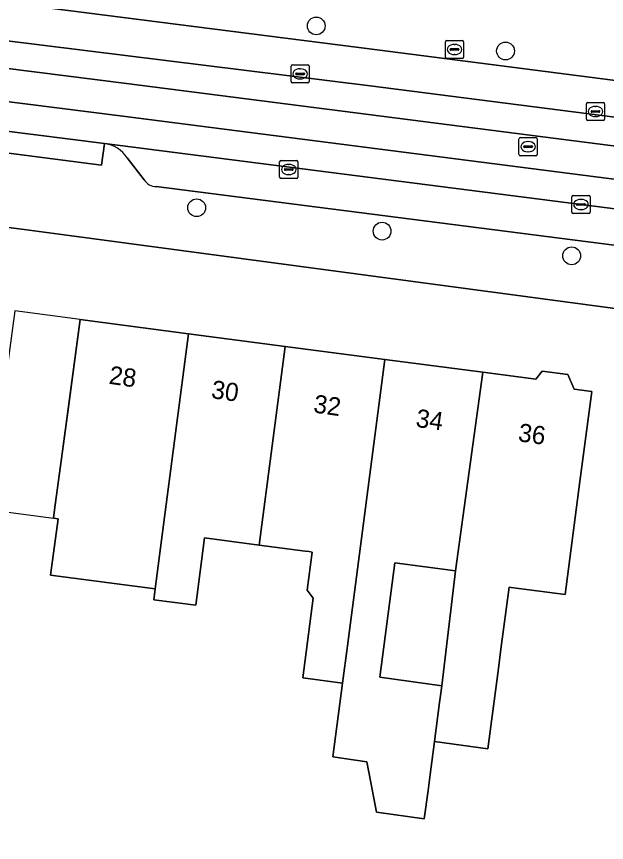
# Model space of a CAD drawing. Extents: x 161692 to 162379, y 380760 to 381678.
# Drawn here: x 161918.27 to 161950.72, y 381271.3 to 381316.74 of the extents above; entities that cross this region are included whole.
import ezdxf

# ---------------------------------------------------------------- set-up
doc = ezdxf.new("R2010")
doc.units = 0
for name, color, linetype in [('IMGEO_Boom', 7, 'Continuous'), ('IMGEO_Brandkraan', 7, 'Continuous'), ('IMGEO_Erf', 7, 'Continuous'), ('IMGEO_Kolk', 7, 'Continuous'), ('IMGEO_Pand', 7, 'Continuous'), ('IMGEO_Pand_nummerreeks', 7, 'Continuous'), ('IMGEO_Pand_overbouw', 7, 'Continuous'), ('IMGEO_Parkeervlak_open', 7, 'Continuous'), ('IMGEO_Rijbaan_lokaal_gesloten', 7, 'Continuous'), ('IMGEO_Rijbaan_lokaal_open', 7, 'Continuous'), ('IMGEO_Rioolput', 7, 'Continuous'), ('IMGEO_Voetpad_open', 7, 'Continuous')]:
    doc.layers.add(name, color=color, linetype=linetype)

msp = doc.modelspace()

# ---------------------------------------------------------------- linework, layer by layer
at = {"layer": 'IMGEO_Boom'}
for centre in [(161934.757, 381316.222), (161945.167, 381314.846), (161928.182, 381306.22), (161938.377, 381304.933), (161948.805, 381303.574)]:
    msp.add_circle(centre, 0.489, dxfattribs=at)
at = {"layer": 'IMGEO_Brandkraan'}
for p, q in [((161941.934, 381315.43), (161942.786, 381315.43)), ((161941.859, 381314.504), (161941.859, 381315.356)), ((161942.118, 381314.924), (161942.118, 381314.936)), ((161942.161, 381314.973), (161942.559, 381314.973)), ((161942.347, 381315.21), (161942.372, 381315.21)), ((161942.602, 381314.936), (161942.602, 381314.924)), ((161942.86, 381315.356), (161942.86, 381314.504)), ((161942.556, 381314.887), (161942.158, 381314.887)), ((161942.37, 381314.65), (161942.345, 381314.65)), ((161942.786, 381314.43), (161941.934, 381314.43))]:
    msp.add_line(p, q, dxfattribs=at)
for points in [[(161941.934, 381315.43), (161942.786, 381315.43)], [(161941.859, 381314.504), (161941.859, 381315.356)], [(161942.86, 381315.356), (161942.86, 381314.504)], [(161942.786, 381314.43), (161941.934, 381314.43)]]:
    msp.add_lwpolyline(points, dxfattribs=at)
for centre, radius, start, end in [((161941.936, 381315.354), 0.0765, 91.552, 178.448), ((161941.936, 381315.354), 0.0765, 91.552, 178.448), ((161942.784, 381315.354), 0.0765, 1.552, 88.448), ((161942.784, 381315.354), 0.0765, 1.552, 88.448), ((161942.158, 381314.933), 0.0403, 85.8775, 175.7526), ((161942.563, 381314.935), 0.0386, 1.7309, 96.639), ((161941.936, 381314.506), 0.0765, 181.552, 268.448), ((161941.936, 381314.506), 0.0765, 181.552, 268.448), ((161942.155, 381314.923), 0.0366, 178.938, 274.7102), ((161942.559, 381314.93), 0.043, 264.8664, 352.4533), ((161942.784, 381314.506), 0.0765, 271.552, 358.448), ((161942.784, 381314.506), 0.0765, 271.552, 358.448)]:
    msp.add_arc(centre, radius, start, end, dxfattribs=at)
for centre, major_axis, ratio, start_param, end_param in [((161942.346, 381314.93), (-0.387, 0.002), 0.722429, 4.712389, 7.853982), ((161942.371, 381314.93), (-0.39, 0.002), 0.717154, 1.570796, 4.712389)]:
    msp.add_ellipse(centre, major_axis=major_axis, ratio=ratio, start_param=start_param, end_param=end_param, dxfattribs=at)
at = {"layer": 'IMGEO_Erf'}
msp.add_lwpolyline([(161867.852, 381207.538), (161977.201, 381250), (161995.053, 381256.932), (162000, 381258.853), (162011.546, 381263.36), (162015.076, 381292.22), (162000, 381294.145), (161921.176, 381304.696), (161918.702, 381305.015), (161871.402, 381311.107)], dxfattribs=at)
for points in [[(161936.202, 381280.054), (161934.023, 381280.36), (161934.594, 381284.745), (161934.254, 381285.183), (161934.527, 381287.278), (161934.374, 381287.298), (161934.15, 381287.327), (161931.624, 381287.657), (161928.615, 381288.051), (161928.132, 381284.353), (161925.822, 381284.655), (161925.899, 381285.247), (161920.139, 381286.001), (161920.559, 381289.105), (161920.299, 381289.139), (161920.36, 381289.591), (161921.106, 381295.112), (161921.775, 381300.067), (161927.732, 381299.288), (161933.052, 381298.591), (161938.529, 381297.875), (161943.91, 381297.171), (161946.835, 381296.788), (161947.176, 381297.233), (161948.599, 381297.047), (161948.933, 381296.242), (161949.909, 381296.114), (161949.26, 381291.157), (161948.447, 381284.941), (161945.482, 381285.322), (161945.36, 381285.338), (161944.916, 381281.938), (161944.777, 381280.872), (161944.199, 381276.447), (161941.258, 381276.859), (161941.021, 381275.043), (161940.904, 381274.147), (161940.701, 381272.592), (161938.076, 381272.96), (161937.756, 381274.589), (161937.53, 381275.74), (161935.674, 381276)], [(161942.415, 381286.245), (161939.084, 381286.681), (161938.263, 381280.386), (161941.656, 381279.91)]]:
    msp.add_lwpolyline(points, close=True, dxfattribs=at)
at = {"layer": 'IMGEO_Kolk'}
for p, q in [((161933.444, 381314.084), (161934.296, 381314.084)), ((161933.369, 381313.158), (161933.369, 381314.01)), ((161933.628, 381313.578), (161933.628, 381313.59)), ((161933.671, 381313.627), (161934.069, 381313.627)), ((161933.857, 381313.864), (161933.882, 381313.864)), ((161934.112, 381313.59), (161934.112, 381313.578)), ((161934.37, 381314.01), (161934.37, 381313.158)), ((161934.066, 381313.541), (161933.668, 381313.541)), ((161933.88, 381313.304), (161933.855, 381313.304)), ((161934.296, 381313.084), (161933.444, 381313.084)), ((161949.613, 381311.089), (161949.613, 381311.941)), ((161949.688, 381312.015), (161950.54, 381312.015)), ((161950.101, 381311.795), (161950.126, 381311.795)), ((161950.614, 381311.941), (161950.614, 381311.089)), ((161949.872, 381311.509), (161949.872, 381311.521)), ((161950.31, 381311.472), (161949.912, 381311.472)), ((161949.915, 381311.558), (161950.313, 381311.558)), ((161950.356, 381311.521), (161950.356, 381311.509)), ((161950.54, 381311.015), (161949.688, 381311.015)), ((161950.124, 381311.235), (161950.099, 381311.235)), ((161932.744, 381307.898), (161932.744, 381308.75)), ((161932.819, 381308.824), (161933.671, 381308.824)), ((161933.232, 381308.604), (161933.257, 381308.604)), ((161933.745, 381308.75), (161933.745, 381307.898)), ((161933.003, 381308.318), (161933.003, 381308.33)), ((161933.441, 381308.281), (161933.043, 381308.281)), ((161933.046, 381308.367), (161933.444, 381308.367)), ((161933.487, 381308.33), (161933.487, 381308.318)), ((161933.671, 381307.824), (161932.819, 381307.824)), ((161933.255, 381308.044), (161933.23, 381308.044)), ((161948.816, 381305.973), (161948.816, 381306.825)), ((161948.891, 381306.899), (161949.743, 381306.899)), ((161949.817, 381306.825), (161949.817, 381305.973)), ((161949.075, 381306.393), (161949.075, 381306.405)), ((161949.513, 381306.356), (161949.115, 381306.356)), ((161949.118, 381306.442), (161949.516, 381306.442)), ((161949.304, 381306.679), (161949.329, 381306.679)), ((161949.559, 381306.405), (161949.559, 381306.393)), ((161949.743, 381305.899), (161948.891, 381305.899)), ((161949.327, 381306.119), (161949.302, 381306.119))]:
    msp.add_line(p, q, dxfattribs=at)
for points in [[(161933.444, 381314.084), (161934.296, 381314.084)], [(161933.369, 381313.158), (161933.369, 381314.01)], [(161934.37, 381314.01), (161934.37, 381313.158)], [(161934.296, 381313.084), (161933.444, 381313.084)], [(161949.613, 381311.089), (161949.613, 381311.941)], [(161949.688, 381312.015), (161950.54, 381312.015)], [(161950.614, 381311.941), (161950.614, 381311.089)], [(161950.54, 381311.015), (161949.688, 381311.015)], [(161932.744, 381307.898), (161932.744, 381308.75)], [(161932.819, 381308.824), (161933.671, 381308.824)], [(161933.745, 381308.75), (161933.745, 381307.898)], [(161933.671, 381307.824), (161932.819, 381307.824)], [(161948.816, 381305.973), (161948.816, 381306.825)], [(161948.891, 381306.899), (161949.743, 381306.899)], [(161949.817, 381306.825), (161949.817, 381305.973)], [(161949.743, 381305.899), (161948.891, 381305.899)]]:
    msp.add_lwpolyline(points, dxfattribs=at)
for centre, radius, start, end in [((161933.446, 381314.008), 0.0765, 91.552, 178.448), ((161933.446, 381314.008), 0.0765, 91.552, 178.448), ((161934.294, 381314.008), 0.0765, 1.552, 88.448), ((161934.294, 381314.008), 0.0765, 1.552, 88.448), ((161933.668, 381313.587), 0.0403, 85.8775, 175.7526), ((161933.665, 381313.577), 0.0366, 178.938, 274.7102), ((161934.069, 381313.584), 0.043, 264.8664, 352.4533), ((161934.073, 381313.589), 0.0386, 1.7309, 96.639), ((161933.446, 381313.16), 0.0765, 181.552, 268.448), ((161933.446, 381313.16), 0.0765, 181.552, 268.448), ((161934.294, 381313.16), 0.0765, 271.552, 358.448), ((161934.294, 381313.16), 0.0765, 271.552, 358.448), ((161949.69, 381311.939), 0.0765, 91.552, 178.448), ((161949.69, 381311.939), 0.0765, 91.552, 178.448), ((161950.538, 381311.939), 0.0765, 1.552, 88.448), ((161950.538, 381311.939), 0.0765, 1.552, 88.448), ((161949.912, 381311.518), 0.0403, 85.8775, 175.7526), ((161949.909, 381311.508), 0.0366, 178.938, 274.7102), ((161950.313, 381311.515), 0.043, 264.8664, 352.4533), ((161950.317, 381311.52), 0.0386, 1.7309, 96.639), ((161949.69, 381311.091), 0.0765, 181.552, 268.448), ((161949.69, 381311.091), 0.0765, 181.552, 268.448), ((161950.538, 381311.091), 0.0765, 271.552, 358.448), ((161950.538, 381311.091), 0.0765, 271.552, 358.448), ((161932.821, 381308.748), 0.0765, 91.552, 178.448), ((161932.821, 381308.748), 0.0765, 91.552, 178.448), ((161933.669, 381308.748), 0.0765, 1.552, 88.448), ((161933.669, 381308.748), 0.0765, 1.552, 88.448), ((161933.043, 381308.327), 0.0403, 85.8775, 175.7526), ((161933.04, 381308.317), 0.0366, 178.938, 274.7102), ((161933.444, 381308.324), 0.043, 264.8664, 352.4533), ((161933.448, 381308.329), 0.0386, 1.7309, 96.639), ((161932.821, 381307.9), 0.0765, 181.552, 268.448), ((161932.821, 381307.9), 0.0765, 181.552, 268.448), ((161933.669, 381307.9), 0.0765, 271.552, 358.448), ((161933.669, 381307.9), 0.0765, 271.552, 358.448), ((161948.893, 381306.823), 0.0765, 91.552, 178.448), ((161948.893, 381306.823), 0.0765, 91.552, 178.448), ((161949.741, 381306.823), 0.0765, 1.552, 88.448), ((161949.741, 381306.823), 0.0765, 1.552, 88.448), ((161949.115, 381306.402), 0.0403, 85.8775, 175.7526), ((161949.112, 381306.392), 0.0366, 178.938, 274.7102), ((161949.516, 381306.399), 0.043, 264.8664, 352.4533), ((161949.52, 381306.404), 0.0386, 1.7309, 96.639), ((161948.893, 381305.975), 0.0765, 181.552, 268.448), ((161948.893, 381305.975), 0.0765, 181.552, 268.448), ((161949.741, 381305.975), 0.0765, 271.552, 358.448), ((161949.741, 381305.975), 0.0765, 271.552, 358.448)]:
    msp.add_arc(centre, radius, start, end, dxfattribs=at)
for centre, major_axis, ratio, start_param, end_param in [((161933.856, 381313.584), (-0.387, 0.002), 0.722429, 4.712389, 7.853982), ((161933.881, 381313.584), (-0.39, 0.002), 0.717154, 1.570796, 4.712389), ((161950.1, 381311.515), (-0.387, 0.002), 0.722429, 4.712389, 7.853982), ((161950.125, 381311.515), (-0.39, 0.002), 0.717154, 1.570796, 4.712389), ((161933.231, 381308.324), (-0.387, 0.002), 0.722429, 4.712389, 7.853982), ((161933.256, 381308.324), (-0.39, 0.002), 0.717154, 1.570796, 4.712389), ((161949.303, 381306.399), (-0.387, 0.002), 0.722429, 4.712389, 7.853982), ((161949.328, 381306.399), (-0.39, 0.002), 0.717154, 1.570796, 4.712389)]:
    msp.add_ellipse(centre, major_axis=major_axis, ratio=ratio, start_param=start_param, end_param=end_param, dxfattribs=at)
at = {"layer": 'IMGEO_Pand'}
for points in [[(161927.732, 381299.288), (161921.775, 381300.067), (161921.106, 381295.112), (161920.36, 381289.591), (161920.299, 381289.139), (161920.559, 381289.105), (161920.139, 381286.001), (161925.899, 381285.247), (161926.304, 381288.353)], [(161933.052, 381298.591), (161927.732, 381299.288), (161926.304, 381288.353), (161925.899, 381285.247), (161925.822, 381284.655), (161928.132, 381284.353), (161928.615, 381288.051), (161931.624, 381287.657)], [(161938.529, 381297.875), (161933.052, 381298.591), (161931.624, 381287.657), (161934.15, 381287.327), (161934.374, 381287.298), (161934.527, 381287.278), (161934.254, 381285.183), (161934.594, 381284.745), (161934.023, 381280.36), (161936.202, 381280.054), (161936.472, 381282.12)], [(161943.91, 381297.171), (161938.529, 381297.875), (161936.472, 381282.12), (161936.202, 381280.054), (161935.674, 381276), (161937.53, 381275.74), (161937.756, 381274.589), (161938.076, 381272.96), (161940.701, 381272.592), (161940.904, 381274.147), (161941.021, 381275.043), (161941.258, 381276.859), (161941.536, 381278.99), (161941.605, 381279.52), (161941.64, 381279.787), (161941.656, 381279.91), (161938.263, 381280.386), (161939.084, 381286.681), (161942.415, 381286.245)], [(161943.91, 381297.171), (161942.415, 381286.245), (161941.656, 381279.91), (161941.64, 381279.787), (161941.605, 381279.52), (161941.536, 381278.99), (161941.258, 381276.859), (161944.199, 381276.447), (161944.777, 381280.872), (161944.916, 381281.938), (161945.36, 381285.338), (161945.482, 381285.322), (161948.447, 381284.941), (161949.26, 381291.157), (161949.909, 381296.114), (161948.933, 381296.242), (161948.599, 381297.047), (161947.176, 381297.233), (161946.835, 381296.788)]]:
    msp.add_lwpolyline(points, close=True, dxfattribs=at)
at = {"layer": 'IMGEO_Pand_overbouw'}
msp.add_lwpolyline([(161921.775, 381300.067), (161918.176, 381300.539), (161916.7, 381289.61), (161920.299, 381289.139)], close=True, dxfattribs=at)
at = {"layer": 'IMGEO_Parkeervlak_open'}
for points in [[(162014.029, 381298.061), (162013.612, 381298.115), (161975.89, 381302.987), (161949.317, 381306.399), (161923.115, 381309.763)], [(161924.366, 381308.964), (161925.293, 381307.759)], [(161925.957, 381307.387), (161975.622, 381301.017), (161981.576, 381300.237), (161987.551, 381299.472), (162010.923, 381296.455)]]:
    msp.add_lwpolyline(points, dxfattribs=at)
for centre, radius, start, end in [((161922.879, 381308.015), 1.764, 32.5451, 82.3231), ((161925.963, 381308.176), 0.789, 211.9134, 269.5679)]:
    msp.add_arc(centre, radius, start, end, dxfattribs=at)
at = {"layer": 'IMGEO_Rijbaan_lokaal_gesloten'}
for points in [[(161938.099, 381314.908), (161875.004, 381322.955), (161874.726, 381320.753), (161937.716, 381312.93), (161976.665, 381307.938), (162014.292, 381303.079), (162014.626, 381303.036)], [(162011.888, 381305.414), (161977.562, 381309.831), (161938.099, 381314.908)]]:
    msp.add_lwpolyline(points, dxfattribs=at)
for points in [[(161937.716, 381312.93), (161874.726, 381320.753), (161874.551, 381319.364), (161924.33, 381313.049), (161976.129, 381306.423), (162014.081, 381301.54), (162014.292, 381303.079), (161976.665, 381307.938)], [(161924.113, 381311.254), (161874.322, 381317.556), (161874.117, 381315.93), (161876.187, 381315.72), (161917.21, 381310.5), (161917.275, 381310.497), (161923.115, 381309.763), (161949.317, 381306.399), (161975.89, 381302.987), (162013.612, 381298.115), (162013.834, 381299.74), (161976.139, 381304.58)]]:
    msp.add_lwpolyline(points, close=True, dxfattribs=at)
at = {"layer": 'IMGEO_Rijbaan_lokaal_open'}
msp.add_lwpolyline([(161874.551, 381319.364), (161874.322, 381317.556), (161924.113, 381311.254), (161976.139, 381304.58), (162013.834, 381299.74), (162014.081, 381301.54), (161976.129, 381306.423), (161924.33, 381313.049)], close=True, dxfattribs=at)
at = {"layer": 'IMGEO_Rioolput'}
for p, q in [((161945.907, 381309.152), (161945.907, 381310.004)), ((161945.982, 381310.078), (161946.834, 381310.078)), ((161946.908, 381310.004), (161946.908, 381309.152)), ((161946.166, 381309.572), (161946.166, 381309.584)), ((161946.604, 381309.535), (161946.206, 381309.535)), ((161946.209, 381309.621), (161946.607, 381309.621)), ((161946.395, 381309.858), (161946.42, 381309.858)), ((161946.65, 381309.584), (161946.65, 381309.572)), ((161946.834, 381309.078), (161945.982, 381309.078)), ((161946.418, 381309.298), (161946.393, 381309.298))]:
    msp.add_line(p, q, dxfattribs=at)
for points in [[(161945.907, 381309.152), (161945.907, 381310.004)], [(161945.982, 381310.078), (161946.834, 381310.078)], [(161946.908, 381310.004), (161946.908, 381309.152)], [(161946.834, 381309.078), (161945.982, 381309.078)]]:
    msp.add_lwpolyline(points, dxfattribs=at)
for centre, radius, start, end in [((161945.984, 381310.002), 0.0765, 91.552, 178.448), ((161945.984, 381310.002), 0.0765, 91.552, 178.448), ((161946.832, 381310.002), 0.0765, 1.552, 88.448), ((161946.832, 381310.002), 0.0765, 1.552, 88.448), ((161946.206, 381309.581), 0.0403, 85.8775, 175.7526), ((161946.203, 381309.571), 0.0366, 178.938, 274.7102), ((161946.607, 381309.578), 0.043, 264.8664, 352.4533), ((161946.611, 381309.583), 0.0386, 1.7309, 96.639), ((161945.984, 381309.154), 0.0765, 181.552, 268.448), ((161945.984, 381309.154), 0.0765, 181.552, 268.448), ((161946.832, 381309.154), 0.0765, 271.552, 358.448), ((161946.832, 381309.154), 0.0765, 271.552, 358.448)]:
    msp.add_arc(centre, radius, start, end, dxfattribs=at)
for centre, major_axis, ratio, start_param, end_param in [((161946.394, 381309.578), (-0.387, 0.002), 0.722429, 4.712389, 7.853982), ((161946.419, 381309.578), (-0.39, 0.002), 0.717154, 1.570796, 4.712389)]:
    msp.add_ellipse(centre, major_axis=major_axis, ratio=ratio, start_param=start_param, end_param=end_param, dxfattribs=at)
at = {"layer": 'IMGEO_Voetpad_open'}
for points in [[(161832.538, 381328.345), (161858.081, 381325.137), (161875.004, 381322.955), (161938.099, 381314.908), (161977.562, 381309.831), (162011.888, 381305.414)], [(161867.278, 381309.693), (161868.344, 381309.528), (161871.402, 381311.107), (161918.702, 381305.015), (161921.176, 381304.696), (162000, 381294.145), (162015.076, 381292.22), (162011.546, 381263.36), (162011.205, 381260.006), (162013.191, 381260.844), (162013.658, 381259.636)], [(161923.115, 381309.763), (161922.944, 381308.561), (161917.119, 381309.318), (161917.275, 381310.497), (161917.21, 381310.5)], [(161925.293, 381307.759), (161924.366, 381308.964)], [(162010.923, 381296.455), (161987.551, 381299.472), (161987.391, 381298.267), (161981.42, 381299.042), (161981.576, 381300.237), (161975.622, 381301.017), (161925.957, 381307.387)]]:
    msp.add_lwpolyline(points, dxfattribs=at)
msp.add_lwpolyline([(161923.115, 381309.763), (161917.275, 381310.497), (161917.119, 381309.318), (161922.944, 381308.561)], close=True, dxfattribs=at)
for centre, radius, start, end in [((161922.879, 381308.015), 1.764, 32.5451, 82.3231), ((161925.963, 381308.176), 0.789, 211.9134, 269.5679)]:
    msp.add_arc(centre, radius, start, end, dxfattribs=at)

# ---------------------------------------------------------------- texts
at = {"layer": 'IMGEO_Pand_nummerreeks'}
for s, p in [('28', (161923.316, 381296.539)), ('30', (161928.943, 381295.748)), ('32', (161934.563, 381294.959)), ('34', (161940.193, 381294.167)), ('36', (161945.82, 381293.377))]:
    msp.add_text(s, height=1, rotation=352.0015, dxfattribs=at).set_placement(p)

doc.saveas('drawing.dxf')
